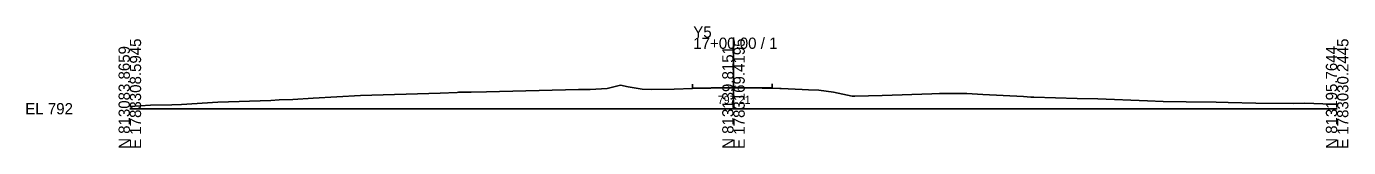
# Model space of a CAD drawing. Extents: x -26 to 1603, y -10 to 6526.
# Drawn here: x 1274.3 to 1602.8, y 3990.3 to 4020.5 of the extents above; entities that cross this region are included whole.
import ezdxf

# ---------------------------------------------------------------- set-up
doc = ezdxf.new("R2010")
doc.units = 0
for name, color, linetype in [('Exist Cross Section Cell', 7, 'Continuous'), ('Exist XS Center Line Elevation Label', 7, 'Continuous'), ('Exist XS Ground Line', 7, 'Continuous'), ('Prop XS EOT Tick Mark', 7, 'Continuous'), ('Prop XS Finish Grade Pavement', 7, 'Continuous')]:
    doc.layers.add(name, color=color, linetype=linetype)

msp = doc.modelspace()

# ---------------------------------------------------------------- linework, layer by layer
at = {"layer": 'Exist Cross Section Cell'}
for p, q in [((1450, 4000), (1450, 4017.71)), ((1300, 4000), (1450, 4000)), ((1450, 4000), (1600, 4000))]:
    msp.add_line(p, q, dxfattribs=at)
at = {"layer": 'Exist XS Ground Line'}
for p, q in [((1414.38, 4004.79), (1418.58, 4005.01)), ((1418.58, 4005.01), (1421.93, 4005.9)), ((1421.93, 4005.9), (1423.84, 4005.42)), ((1423.84, 4005.42), (1427.29, 4004.87)), ((1427.29, 4004.87), (1429.62, 4004.78)), ((1429.62, 4004.78), (1435.27, 4004.9)), ((1435.27, 4004.9), (1439.8, 4005.02)), ((1439.8, 4005.02), (1449.04, 4005.2)), ((1449.04, 4005.2), (1449.87, 4005.22)), ((1449.87, 4005.22), (1451.48, 4005.19)), ((1451.48, 4005.19), (1457.14, 4005.12)), ((1457.14, 4005.12), (1459.29, 4005.08)), ((1459.29, 4005.08), (1461.5, 4005.03)), ((1461.5, 4005.03), (1461.86, 4005.02)), ((1461.86, 4005.02), (1467.05, 4004.78)), ((1312.85, 4001.08), (1321.86, 4001.61)), ((1321.86, 4001.61), (1335, 4002.08)), ((1335, 4002.08), (1337.12, 4002.21)), ((1337.12, 4002.21), (1340.47, 4002.3)), ((1340.47, 4002.3), (1345.52, 4002.66)), ((1345.52, 4002.66), (1357.31, 4003.28)), ((1357.31, 4003.28), (1377.1, 4003.87)), ((1377.1, 4003.87), (1381.33, 4004.07)), ((1381.33, 4004.07), (1381.65, 4004.08)), ((1381.65, 4004.08), (1384.79, 4004.12)), ((1384.79, 4004.12), (1388.59, 4004.23)), ((1388.59, 4004.23), (1411.51, 4004.78)), ((1411.51, 4004.78), (1414.38, 4004.79)), ((1467.05, 4004.78), (1468.68, 4004.69)), ((1468.68, 4004.69), (1471.21, 4004.58)), ((1471.21, 4004.58), (1474.88, 4004.14)), ((1474.88, 4004.14), (1479.48, 4003.15)), ((1479.48, 4003.15), (1480.13, 4003.15)), ((1480.13, 4003.15), (1486.95, 4003.32)), ((1486.95, 4003.32), (1499.27, 4003.7)), ((1499.27, 4003.7), (1501.19, 4003.75)), ((1501.19, 4003.75), (1502.72, 4003.81)), ((1502.72, 4003.81), (1507.97, 4003.78)), ((1507.97, 4003.78), (1511.96, 4003.58)), ((1511.96, 4003.58), (1522.03, 4003.01)), ((1522.03, 4003.01), (1523.86, 4002.91)), ((1523.86, 4002.91), (1524.6, 4002.89)), ((1524.6, 4002.89), (1535.37, 4002.52)), ((1535.37, 4002.52), (1540.56, 4002.48)), ((1540.56, 4002.48), (1552.88, 4001.95)), ((1552.88, 4001.95), (1556.8, 4001.82)), ((1556.8, 4001.82), (1562.5, 4001.69)), ((1562.5, 4001.69), (1569.95, 4001.59)), ((1569.95, 4001.59), (1572.96, 4001.55)), ((1572.96, 4001.55), (1579.81, 4001.42)), ((1300, 4000.54), (1305.13, 4000.88)), ((1305.13, 4000.88), (1310.42, 4000.96)), ((1310.42, 4000.96), (1312.85, 4001.08)), ((1579.81, 4001.42), (1589.07, 4001.27)), ((1589.07, 4001.27), (1591.95, 4001.34)), ((1591.95, 4001.34), (1596.43, 4001.2)), ((1596.43, 4001.2), (1600, 4001.1))]:
    msp.add_line(p, q, dxfattribs=at)
at = {"layer": 'Prop XS EOT Tick Mark'}
for p, q in [((1439.8, 4005.14), (1439.8, 4006.14)), ((1459.59, 4005.2), (1459.59, 4006.2))]:
    msp.add_line(p, q, dxfattribs=at)
at = {"layer": 'Prop XS Finish Grade Pavement'}
for p, q in [((1439.8, 4005.14), (1449.04, 4005.32)), ((1449.04, 4005.32), (1449.87, 4005.34)), ((1449.87, 4005.34), (1451.48, 4005.32)), ((1451.48, 4005.32), (1457.14, 4005.24)), ((1457.14, 4005.24), (1459.29, 4005.21)), ((1459.29, 4005.21), (1459.59, 4005.2))]:
    msp.add_line(p, q, dxfattribs=at)

# ---------------------------------------------------------------- texts
at = {"layer": 'Exist Cross Section Cell'}
for s, p in [('Y5', (1440, 4017.71)), ('17+00.00 / 1', (1440, 4014.91)), ('EL 792', (1274, 3998.6))]:
    msp.add_text(s, height=2.8, dxfattribs=at).set_placement(p)
for s, p in [('N 813083.8659', (1300, 3990)), ('E 1783308.5945', (1302.8, 3990)), ('N 813139.8151', (1450, 3990)), ('E 1783169.4195', (1452.8, 3990)), ('N 813195.7644', (1600, 3990)), ('E 1783030.2445', (1602.8, 3990))]:
    msp.add_text(s, height=2.8, rotation=90, dxfattribs=at).set_placement(p)
at = {"layer": 'Exist XS Center Line Elevation Label'}
msp.add_text('797.21', height=2, dxfattribs=at).set_placement((1446.08, 4001.21))

doc.saveas('drawing.dxf')
